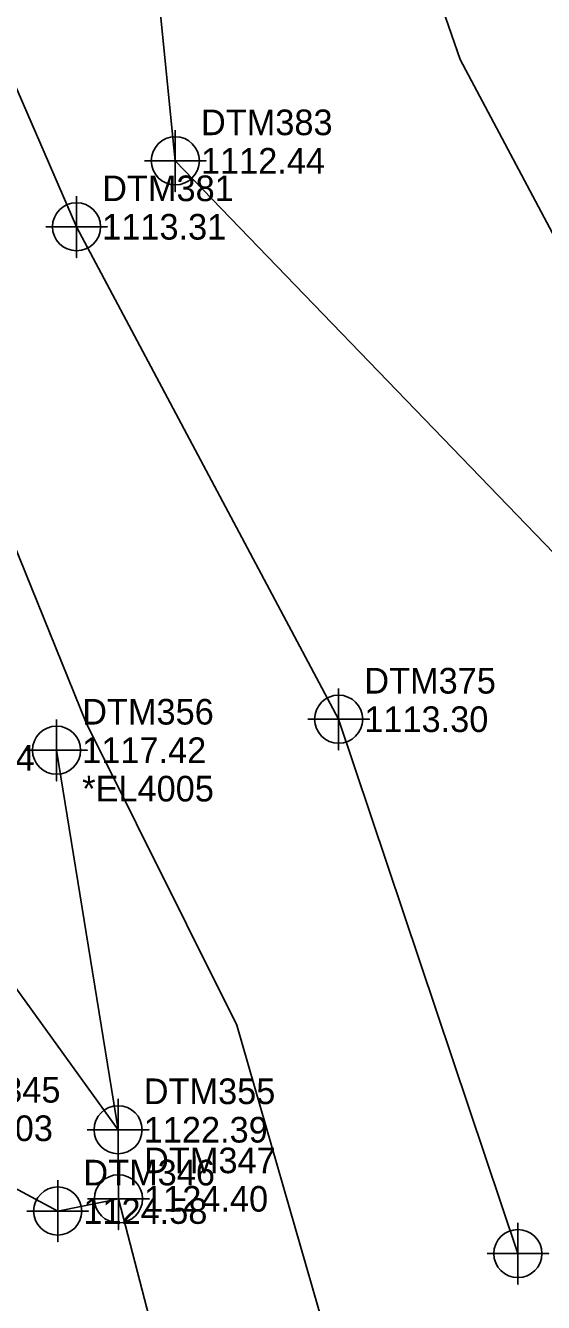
# Model space of a CAD drawing. Extents: x 1286409 to 1286829, y 857931 to 858308.
# Drawn here: x 1286598.7 to 1286649.1, y 858032.3 to 858156.8 of the extents above; entities that cross this region are included whole.
import ezdxf

# ---------------------------------------------------------------- set-up
doc = ezdxf.new("R2010")
doc.units = 0
for name, color, linetype in [('Exist DTM Breakline', 7, 'Continuous'), ('Exist DTM Breakline Cogo Comment', 7, 'Continuous'), ('Exist DTM Breakline Cogo Elevation', 7, 'Continuous'), ('Exist DTM Breakline Cogo Number', 7, 'Continuous'), ('Exist DTM Breakline Cogo Point CELL', 7, 'Continuous'), ('Exist DTM Breakline Underwater', 7, 'Continuous'), ('Exist DTM Breakline Underwater Cogo Elevation', 7, 'Continuous'), ('Exist DTM Breakline Underwater Cogo Number', 7, 'Continuous'), ('Exist DTM Breakline Underwater Cogo Point CELL', 7, 'Continuous'), ('Exist Hydro Stream or Body of Water', 7, 'Continuous')]:
    doc.layers.add(name, color=color, linetype=linetype)

msp = doc.modelspace()

# ---------------------------------------------------------------- linework, layer by layer
at = {"layer": 'Exist DTM Breakline'}
for points in [[(1286536.003, 858236.961), (1286552.055, 858201.893), (1286559.903, 858160.92), (1286565.827, 858147.987), (1286576.897, 858124.766), (1286579.562, 858099.067), (1286584.222, 858081.673), (1286607.668, 858049.163), (1286601.672, 858086.174)], [(1286530.298, 858233.7), (1286543.261, 858195.881), (1286559.854, 858160.955), (1286563.292, 858147.427), (1286569.804, 858128.536), (1286569.528, 858112.107), (1286564.126, 858113.252), (1286558.412, 858113.755), (1286552.418, 858104.363), (1286554.757, 858095.462), (1286567.776, 858091.209), (1286569.105, 858068.653), (1286573.239, 858056.109), (1286586.738, 858049.307), (1286601.784, 858041.235), (1286607.702, 858042.424), (1286614.823, 858014.95)]]:
    msp.add_lwpolyline(points, dxfattribs=at)
at = {"layer": 'Exist DTM Breakline Cogo Point CELL'}
for points in [[(1286601.672, 858089.174), (1286601.672, 858083.174), (1286601.672, 858086.174), (1286604.672, 858086.174), (1286598.672, 858086.174)], [(1286607.668, 858052.163), (1286607.668, 858046.163), (1286607.668, 858049.163), (1286610.668, 858049.163), (1286604.668, 858049.163)], [(1286607.702, 858045.424), (1286607.702, 858039.424), (1286607.702, 858042.424), (1286610.702, 858042.424), (1286604.702, 858042.424)], [(1286601.784, 858044.235), (1286601.784, 858038.235), (1286601.784, 858041.235), (1286604.784, 858041.235), (1286598.784, 858041.235)]]:
    msp.add_lwpolyline(points, dxfattribs=at)
for centre in [(1286601.672, 858086.174), (1286607.668, 858049.163), (1286607.702, 858042.424), (1286601.784, 858041.235)]:
    msp.add_circle(centre, 2.344, dxfattribs=at)
at = {"layer": 'Exist DTM Breakline Underwater'}
for points in [[(1286669.815, 858058.251), (1286654.631, 858100.703), (1286613.243, 858143.649), (1286609.52, 858180.682), (1286592.241, 858242.731), (1286573.236, 858288.883)], [(1286646.614, 858037.087), (1286629.153, 858089.196), (1286603.619, 858137.215), (1286590.426, 858167.626), (1286563.88, 858237.106), (1286548.712, 858281.174)]]:
    msp.add_lwpolyline(points, dxfattribs=at)
at = {"layer": 'Exist DTM Breakline Underwater Cogo Point CELL'}
for points in [[(1286613.243, 858146.649), (1286613.243, 858140.649), (1286613.243, 858143.649), (1286616.243, 858143.649), (1286610.243, 858143.649)], [(1286603.619, 858140.215), (1286603.619, 858134.215), (1286603.619, 858137.215), (1286606.619, 858137.215), (1286600.619, 858137.215)], [(1286629.153, 858092.196), (1286629.153, 858086.196), (1286629.153, 858089.196), (1286632.153, 858089.196), (1286626.153, 858089.196)], [(1286646.614, 858040.087), (1286646.614, 858034.087), (1286646.614, 858037.087), (1286649.614, 858037.087), (1286643.614, 858037.087)]]:
    msp.add_lwpolyline(points, dxfattribs=at)
for centre in [(1286613.243, 858143.649), (1286603.619, 858137.215), (1286629.153, 858089.196), (1286646.614, 858037.087)]:
    msp.add_circle(centre, 2.344, dxfattribs=at)
at = {"layer": 'Exist Hydro Stream or Body of Water'}
for points in [[(1286685.865, 858065.012), (1286665.776, 858106.892), (1286641.007, 858153.512), (1286624.223, 858201.931), (1286608.049, 858245.959), (1286588.044, 858292.077)], [(1286633.369, 858010.272), (1286619.226, 858059.374), (1286604.574, 858088.843), (1286588.568, 858128.319), (1286577.591, 858159.308), (1286547.36, 858229.805), (1286531.042, 858265.146)]]:
    msp.add_lwpolyline(points, dxfattribs=at)

# ---------------------------------------------------------------- texts
at = {"layer": 'Exist DTM Breakline Cogo Comment'}
msp.add_text('*EL4005', height=2.5, dxfattribs=at).set_placement((1286604.172, 858081.174))
at = {"layer": 'Exist DTM Breakline Cogo Elevation'}
for s, p in [('1117.42', (1286604.172, 858084.924)), ('1129.03', (1286589.238, 858048.057)), ('1122.39', (1286610.168, 858047.913)), ('1124.40', (1286610.202, 858041.174)), ('1124.58', (1286604.284, 858039.985))]:
    msp.add_text(s, height=2.5, dxfattribs=at).set_placement(p)
at = {"layer": 'Exist DTM Breakline Cogo Number'}
for s, p in [('DTM356', (1286604.172, 858088.674)), ('DTM354', (1286586.722, 858084.173)), ('DTM345', (1286589.238, 858051.807)), ('DTM355', (1286610.168, 858051.663)), ('DTM347', (1286610.202, 858044.924)), ('DTM346', (1286604.284, 858043.735))]:
    msp.add_text(s, height=2.5, dxfattribs=at).set_placement(p)
at = {"layer": 'Exist DTM Breakline Underwater Cogo Elevation'}
for s, p in [('1112.44', (1286615.743, 858142.399)), ('1113.31', (1286606.119, 858135.965)), ('1113.30', (1286631.653, 858087.946))]:
    msp.add_text(s, height=2.5, dxfattribs=at).set_placement(p)
at = {"layer": 'Exist DTM Breakline Underwater Cogo Number'}
for s, p in [('DTM383', (1286615.743, 858146.149)), ('DTM381', (1286606.119, 858139.715)), ('DTM375', (1286631.653, 858091.696))]:
    msp.add_text(s, height=2.5, dxfattribs=at).set_placement(p)

doc.saveas('drawing.dxf')
